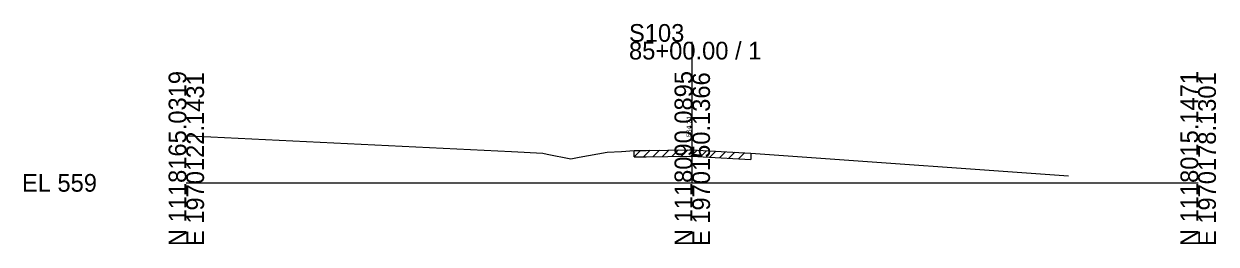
# Model space of a CAD drawing. Extents: x -26 to 163, y -10 to 45020.
# Drawn here: x -25.7 to 162.8, y 43990.3 to 44025.1 of the extents above; entities that cross this region are included whole.
import ezdxf

# ---------------------------------------------------------------- set-up
doc = ezdxf.new("R2010")
doc.units = 0
for name, color, linetype in [('RD_GPK_XS_Cell', 7, 'Continuous'), ('RD_XS_ExGround', 7, 'Continuous'), ('RD_XS_ExPaveRet', 7, 'Continuous'), ('RD_XS_TX_Elev_EX', 7, 'Continuous')]:
    doc.layers.add(name, color=color, linetype=linetype)

msp = doc.modelspace()

# ---------------------------------------------------------------- linework, layer by layer
at = {"layer": 'RD_GPK_XS_Cell'}
for p, q in [((80, 44000), (80, 44022.31)), ((0, 44000), (80, 44000)), ((80, 44000), (160, 44000))]:
    msp.add_line(p, q, dxfattribs=at)
at = {"layer": 'RD_XS_ExGround'}
for p, q in [((0, 44007.44), (3.86, 44007.28)), ((3.86, 44007.28), (51.42, 44004.95)), ((51.42, 44004.95), (56.36, 44004.67)), ((56.36, 44004.67), (57.07, 44004.54)), ((57.07, 44004.54), (60.8, 44003.82)), ((60.8, 44003.82), (62.12, 44004.08)), ((62.12, 44004.08), (66.54, 44004.83)), ((66.54, 44004.83), (68.8, 44004.98)), ((68.8, 44004.98), (70.8, 44005.11)), ((70.8, 44005.11), (72.71, 44005.14)), ((72.71, 44005.14), (79.55, 44005.24)), ((79.55, 44005.24), (80, 44005.21)), ((80, 44005.21), (81.72, 44005.11)), ((81.72, 44005.11), (89.26, 44004.7)), ((89.26, 44004.7), (95.15, 44004.29)), ((95.15, 44004.29), (139.48, 44001.12))]:
    msp.add_line(p, q, dxfattribs=at)
at = {"layer": 'RD_XS_ExPaveRet'}
for p, q in [((70.8, 44004.11), (71.82, 44005.13)), ((70.8, 44004.11), (70.8, 44005.11)), ((70.8, 44004.11), (72.71, 44004.14)), ((72.3, 44004.13), (73.32, 44005.15)), ((72.71, 44004.14), (79.55, 44004.24)), ((73.8, 44004.15), (74.82, 44005.17)), ((75.3, 44004.18), (76.32, 44005.19)), ((76.8, 44004.2), (77.82, 44005.21)), ((78.3, 44004.22), (79.32, 44005.24)), ((79.55, 44004.24), (80, 44004.21)), ((79.8, 44004.23), (80.75, 44005.17)), ((80, 44004.21), (81.72, 44004.11)), ((81.3, 44004.14), (82.25, 44005.09)), ((81.72, 44004.11), (89.26, 44003.7)), ((82.8, 44004.06), (83.75, 44005)), ((84.3, 44003.97), (85.25, 44004.92)), ((85.8, 44003.89), (86.75, 44004.84)), ((87.3, 44003.81), (88.25, 44004.76)), ((89.26, 44004.7), (89.26, 44003.7))]:
    msp.add_line(p, q, dxfattribs=at)

# ---------------------------------------------------------------- texts
at = {"layer": 'RD_GPK_XS_Cell'}
for s, p in [('S103', (70, 44022.31)), ('85+00.00 / 1', (70, 44019.51)), ('EL 559', (-26, 43998.6))]:
    msp.add_text(s, height=2.8, dxfattribs=at).set_placement(p)
for s, p in [('N 1118165.0319', (0, 43990)), ('E 1970122.1431', (2.8, 43990)), ('N 1118090.0895', (80, 43990)), ('E 1970150.1366', (82.8, 43990)), ('N 1118015.1471', (160, 43990)), ('E 1970178.1301', (162.8, 43990))]:
    msp.add_text(s, height=2.8, rotation=90, dxfattribs=at).set_placement(p)
at = {"layer": 'RD_XS_TX_Elev_EX'}
msp.add_text('564.21', height=0.8, rotation=90, dxfattribs=at).set_placement((79.9, 44007.21))

doc.saveas('drawing.dxf')
